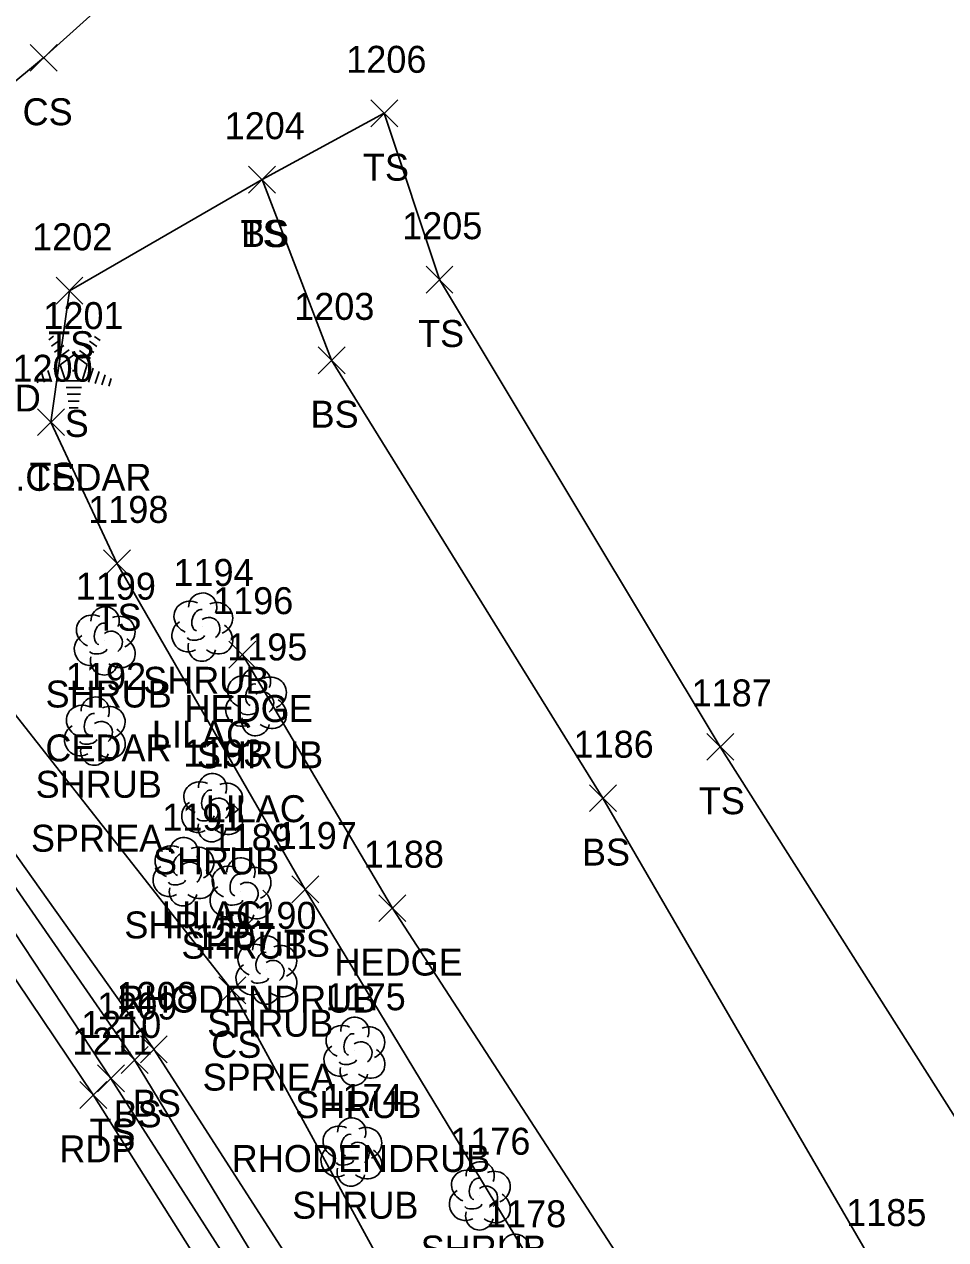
# Model space of a CAD drawing. Extents: x 1501299 to 1502485, y 381423 to 383765.
# Drawn here: x 1501819.8 to 1501888.1, y 382999.5 to 383089.7 of the extents above; entities that cross this region are included whole.
import ezdxf

# ---------------------------------------------------------------- set-up
doc = ezdxf.new("R2010")
doc.units = 0
for name, color, linetype in [('L_A', 7, 'Continuous'), ('L_C', 7, 'Continuous'), ('L_I', 7, 'Continuous'), ('L_TIC', 7, 'Continuous'), ('LAHR', 7, 'Continuous'), ('LELB', 7, 'Continuous'), ('LSH', 7, 'Continuous'), ('LTC', 7, 'Continuous'), ('P_A', 7, 'Continuous'), ('P_I', 7, 'Continuous'), ('P_TIC', 7, 'Continuous'), ('PET', 7, 'Continuous')]:
    doc.layers.add(name, color=color, linetype=linetype)

msp = doc.modelspace()

# ---------------------------------------------------------------- linework, layer by layer
at = {"layer": 'L_TIC'}
for points in [[(1501820.181, 383086.198), (1501822.181, 383088.198)], [(1501822.181, 383086.198), (1501820.181, 383088.198)], [(1501845.451, 383082.089), (1501847.451, 383084.089)], [(1501847.451, 383082.089), (1501845.451, 383084.089)], [(1501845.451, 383082.089), (1501847.451, 383084.089)], [(1501847.451, 383082.089), (1501845.451, 383084.089)], [(1501836.382, 383077.164), (1501838.382, 383079.164)], [(1501838.382, 383077.164), (1501836.382, 383079.164)], [(1501836.382, 383077.164), (1501838.382, 383079.164)], [(1501838.382, 383077.164), (1501836.382, 383079.164)], [(1501849.544, 383069.745), (1501851.544, 383071.745)], [(1501851.544, 383069.745), (1501849.544, 383071.745)], [(1501822.102, 383068.918), (1501824.102, 383070.918)], [(1501824.102, 383068.918), (1501822.102, 383070.918)], [(1501841.537, 383063.759), (1501843.537, 383065.759)], [(1501843.537, 383063.759), (1501841.537, 383065.759)], [(1501820.728, 383059.169), (1501822.728, 383061.169)], [(1501822.728, 383059.169), (1501820.728, 383061.169)], [(1501825.615, 383048.697), (1501827.615, 383050.697)], [(1501827.615, 383048.697), (1501825.615, 383050.697)], [(1501834.929, 383041.926), (1501836.929, 383043.926)], [(1501836.929, 383041.926), (1501834.929, 383043.926)], [(1501870.363, 383035.084), (1501872.363, 383037.084)], [(1501872.363, 383035.084), (1501870.363, 383037.084)], [(1501861.664, 383031.275), (1501863.664, 383033.275)], [(1501863.664, 383031.275), (1501861.664, 383033.275)], [(1501839.589, 383024.507), (1501841.589, 383026.507)], [(1501841.589, 383024.507), (1501839.589, 383026.507)], [(1501846.051, 383023.115), (1501848.051, 383025.115)], [(1501848.051, 383023.115), (1501846.051, 383025.115)], [(1501834.173, 383017.012), (1501836.173, 383019.012)], [(1501836.173, 383017.012), (1501834.173, 383019.012)], [(1501828.357, 383012.645), (1501830.357, 383014.645)], [(1501830.357, 383012.645), (1501828.357, 383014.645)], [(1501826.93, 383011.856), (1501828.93, 383013.856)], [(1501828.93, 383011.856), (1501826.93, 383013.856)], [(1501825.17, 383010.487), (1501827.17, 383012.487)], [(1501827.17, 383010.487), (1501825.17, 383012.487)]]:
    msp.add_lwpolyline(points, dxfattribs=at)
at = {"layer": 'LAHR'}
msp.add_lwpolyline([(1501886.886, 382958.595), (1501878.558, 382964.802), (1501870.803, 382987.478), (1501847.051, 383024.115), (1501835.929, 383042.926)], dxfattribs=at)
at = {"layer": 'LELB'}
for points in [[(1501869.881, 382950.686), (1501868.769, 382950.2), (1501850.126, 382976.258), (1501827.93, 383012.856), (1501805.246, 383045.654), (1501793.264, 383066.917), (1501794.32, 383067.431), (1501799.894, 383080.741), (1501815.831, 383095.832), (1501838.892, 383122.309)], [(1501872.664, 382953.638), (1501855.947, 382979.919), (1501835.173, 383018.012), (1501808.759, 383051.568), (1501808.19, 383064.923), (1501807.021, 383075.451), (1501821.181, 383087.198), (1501841.551, 383105.554)], [(1501860.53, 382958.003), (1501859.863, 382956.699), (1501869.315, 382947.686), (1501873.642, 382949.922), (1501872.664, 382953.638), (1501875.496, 382965.587), (1501865.678, 382984.07), (1501840.589, 383025.507), (1501826.615, 383049.697), (1501821.728, 383060.169), (1501823.102, 383069.918), (1501837.382, 383078.164), (1501846.451, 383083.089)], [(1501875.496, 382965.587), (1501878.558, 382964.802), (1501896.791, 382979.516), (1501894.945, 382998.888), (1501871.363, 383036.084), (1501850.544, 383070.745), (1501846.451, 383083.089)], [(1501860.53, 382958.003), (1501849.203, 382975.471), (1501826.17, 383011.487), (1501803.928, 383045.204), (1501790.589, 383066.151), (1501793.35, 383069.124), (1501796.83, 383082.637)], [(1501869.881, 382950.686), (1501852.369, 382977.849), (1501829.357, 383013.645), (1501805.875, 383046.715), (1501796.137, 383066.958), (1501799.894, 383080.741)], [(1501896.791, 382979.516), (1501889.637, 382987.154), (1501882.83, 382997.53), (1501862.664, 383032.275), (1501842.537, 383064.759), (1501837.382, 383078.164)]]:
    msp.add_lwpolyline(points, dxfattribs=at)
at = {"layer": 'LSH'}
for p, q in [((1501832.935, 383045.019), (1501832.935, 383045.019)), ((1501832.935, 383045.019), (1501832.935, 383045.019)), ((1501825.696, 383044.001), (1501825.696, 383044.001)), ((1501825.696, 383044.001), (1501825.696, 383044.001)), ((1501836.92, 383039.494), (1501836.92, 383039.494)), ((1501836.92, 383039.494), (1501836.92, 383039.494)), ((1501824.958, 383037.303), (1501824.958, 383037.303)), ((1501824.958, 383037.303), (1501824.958, 383037.303)), ((1501833.664, 383031.619), (1501833.664, 383031.619)), ((1501833.664, 383031.619), (1501833.664, 383031.619)), ((1501831.537, 383026.87), (1501831.537, 383026.87)), ((1501831.537, 383026.87), (1501831.537, 383026.87)), ((1501835.77, 383025.367), (1501835.77, 383025.367)), ((1501835.77, 383025.367), (1501835.77, 383025.367)), ((1501837.684, 383019.58), (1501837.684, 383019.58)), ((1501837.684, 383019.58), (1501837.684, 383019.58)), ((1501844.213, 383013.541), (1501844.213, 383013.541)), ((1501844.213, 383013.541), (1501844.213, 383013.541)), ((1501843.989, 383006.078), (1501843.989, 383006.078)), ((1501843.989, 383006.078), (1501843.989, 383006.078)), ((1501853.515, 383002.824), (1501853.515, 383002.824)), ((1501853.515, 383002.824), (1501853.515, 383002.824))]:
    msp.add_line(p, q, dxfattribs=at)
for centre in [(1501832.982, 383046.453), (1501825.743, 383045.435), (1501836.967, 383040.928), (1501825.005, 383038.737), (1501833.711, 383033.053), (1501831.583, 383028.304), (1501835.817, 383026.801), (1501837.731, 383021.014), (1501844.26, 383014.975), (1501844.035, 383007.512), (1501853.562, 383004.258), (1501856.163, 382998.878)]:
    msp.add_arc(centre, 1.047, 335.52715, 180.95627, dxfattribs=at)
for centre, major_axis, ratio, start_param, end_param in [((1501832.143, 383045.685), (1.21, -0.512), 0.895232, 1.570796, 4.712389), ((1501832.726, 383045.477), (-0.208, -0.792), 0.645439, 3.141593, 6.283185), ((1501833.976, 383045.602), (-1.141, -0.483), 0.949671, 1.570796, 4.712389), ((1501824.904, 383044.667), (1.21, -0.512), 0.895232, 1.570796, 4.712389), ((1501825.488, 383044.459), (-0.208, -0.792), 0.645439, 3.141593, 6.283185), ((1501826.738, 383044.584), (-1.141, -0.483), 0.949671, 1.570796, 4.712389), ((1501831.852, 383044.31), (0.584, -1.042), 0.959034, 3.141593, 6.283185), ((1501833.435, 383044.852), (-0.5, 0.667), 0.989748, 3.141593, 6.283185), ((1501824.613, 383043.292), (0.584, -1.042), 0.959034, 3.141593, 6.283185), ((1501826.196, 383043.834), (-0.5, 0.667), 0.989748, 3.141593, 6.283185), ((1501832.477, 383044.269), (-0.625, -0.083), 0.423636, 0, 3.141593), ((1501833.935, 383044.186), (-1.09, 0.792), 0.841452, 1.570796, 4.712389), ((1501826.696, 383043.167), (-1.09, 0.792), 0.841452, 1.570796, 4.712389), ((1501832.935, 383043.519), (0.265, 1.061), 0.942809, 1.570796, 4.712389), ((1501825.696, 383042.501), (0.265, 1.061), 0.942809, 1.570796, 4.712389), ((1501825.238, 383043.251), (-0.625, -0.083), 0.423636, 0, 3.141593), ((1501836.128, 383040.16), (1.21, -0.512), 0.895232, 1.570796, 4.712389), ((1501836.711, 383039.952), (-0.208, -0.792), 0.645439, 3.141593, 6.283185), ((1501837.961, 383040.077), (-1.141, -0.483), 0.949671, 1.570796, 4.712389), ((1501835.837, 383038.785), (0.584, -1.042), 0.959034, 3.141593, 6.283185), ((1501837.42, 383039.327), (-0.5, 0.667), 0.989748, 3.141593, 6.283185), ((1501824.166, 383037.969), (1.21, -0.512), 0.895232, 1.570796, 4.712389), ((1501826, 383037.886), (-1.141, -0.483), 0.949671, 1.570796, 4.712389), ((1501837.92, 383038.661), (-1.09, 0.792), 0.841452, 1.570796, 4.712389), ((1501824.75, 383037.761), (-0.208, -0.792), 0.645439, 3.141593, 6.283185), ((1501825.458, 383037.136), (-0.5, 0.667), 0.989748, 3.141593, 6.283185), ((1501836.92, 383037.994), (0.265, 1.061), 0.942809, 1.570796, 4.712389), ((1501836.462, 383038.744), (-0.625, -0.083), 0.423636, 0, 3.141593), ((1501823.875, 383036.594), (0.584, -1.042), 0.959034, 3.141593, 6.283185), ((1501825.958, 383036.47), (-1.09, 0.792), 0.841452, 1.570796, 4.712389), ((1501824.5, 383036.553), (-0.625, -0.083), 0.423636, 0, 3.141593), ((1501824.958, 383035.803), (0.265, 1.061), 0.942809, 1.570796, 4.712389), ((1501832.873, 383032.286), (1.21, -0.512), 0.895232, 1.570796, 4.712389), ((1501834.706, 383032.203), (-1.141, -0.483), 0.949671, 1.570796, 4.712389), ((1501833.456, 383032.077), (-0.208, -0.792), 0.645439, 3.141593, 6.283185), ((1501832.581, 383030.91), (0.584, -1.042), 0.959034, 3.141593, 6.283185), ((1501834.165, 383031.452), (-0.5, 0.667), 0.989748, 3.141593, 6.283185), ((1501834.665, 383030.786), (-1.09, 0.792), 0.841452, 1.570796, 4.712389), ((1501833.206, 383030.869), (-0.625, -0.083), 0.423636, 0, 3.141593), ((1501833.665, 383030.119), (0.265, 1.061), 0.942809, 1.570796, 4.712389), ((1501830.745, 383027.537), (1.21, -0.512), 0.895232, 1.570796, 4.712389), ((1501831.328, 383027.329), (-0.208, -0.792), 0.645439, 3.141593, 6.283185), ((1501832.578, 383027.454), (-1.141, -0.483), 0.949671, 1.570796, 4.712389), ((1501830.454, 383026.162), (0.584, -1.042), 0.959034, 3.141593, 6.283185), ((1501832.037, 383026.704), (-0.5, 0.667), 0.989748, 3.141593, 6.283185), ((1501834.978, 383026.033), (1.21, -0.512), 0.895232, 1.570796, 4.712389), ((1501836.812, 383025.95), (-1.141, -0.483), 0.949671, 1.570796, 4.712389), ((1501832.537, 383026.037), (-1.09, 0.792), 0.841452, 1.570796, 4.712389), ((1501835.562, 383025.825), (-0.208, -0.792), 0.645439, 3.141593, 6.283185), ((1501831.537, 383025.37), (0.265, 1.061), 0.942809, 1.570796, 4.712389), ((1501831.079, 383026.12), (-0.625, -0.083), 0.423636, 0, 3.141593), ((1501834.687, 383024.658), (0.584, -1.042), 0.959034, 3.141593, 6.283185), ((1501836.27, 383025.2), (-0.5, 0.667), 0.989748, 3.141593, 6.283185), ((1501836.77, 383024.534), (-1.09, 0.792), 0.841452, 1.570796, 4.712389), ((1501835.312, 383024.617), (-0.625, -0.083), 0.423636, 0, 3.141593), ((1501835.77, 383023.867), (0.265, 1.061), 0.942809, 1.570796, 4.712389), ((1501836.892, 383020.247), (1.21, -0.512), 0.895232, 1.570796, 4.712389), ((1501837.475, 383020.039), (-0.208, -0.792), 0.645439, 3.141593, 6.283185), ((1501838.725, 383020.164), (-1.141, -0.483), 0.949671, 1.570796, 4.712389), ((1501836.601, 383018.872), (0.584, -1.042), 0.959034, 3.141593, 6.283185), ((1501838.184, 383019.414), (-0.5, 0.667), 0.989748, 3.141593, 6.283185), ((1501838.684, 383018.747), (-1.09, 0.792), 0.841452, 1.570796, 4.712389), ((1501837.684, 383018.08), (0.265, 1.061), 0.942809, 1.570796, 4.712389), ((1501837.226, 383018.83), (-0.625, -0.083), 0.423636, 0, 3.141593), ((1501843.421, 383014.207), (1.21, -0.512), 0.895232, 1.570796, 4.712389), ((1501845.255, 383014.124), (-1.141, -0.483), 0.949671, 1.570796, 4.712389), ((1501844.005, 383013.999), (-0.208, -0.792), 0.645439, 3.141593, 6.283185), ((1501843.13, 383012.832), (0.584, -1.042), 0.959034, 3.141593, 6.283185), ((1501844.713, 383013.374), (-0.5, 0.667), 0.989748, 3.141593, 6.283185), ((1501845.213, 383012.707), (-1.09, 0.792), 0.841452, 1.570796, 4.712389), ((1501843.755, 383012.791), (-0.625, -0.083), 0.423636, 0, 3.141593), ((1501844.213, 383012.041), (0.265, 1.061), 0.942809, 1.570796, 4.712389), ((1501843.197, 383006.745), (1.21, -0.512), 0.895232, 1.570796, 4.712389), ((1501843.78, 383006.536), (-0.208, -0.792), 0.645439, 3.141593, 6.283185), ((1501845.03, 383006.662), (-1.141, -0.483), 0.949671, 1.570796, 4.712389), ((1501842.906, 383005.37), (0.584, -1.042), 0.959034, 3.141593, 6.283185), ((1501844.489, 383005.912), (-0.5, 0.667), 0.989748, 3.141593, 6.283185), ((1501844.989, 383005.245), (-1.09, 0.792), 0.841452, 1.570796, 4.712389), ((1501843.989, 383004.578), (0.265, 1.061), 0.942809, 1.570796, 4.712389), ((1501843.531, 383005.328), (-0.625, -0.083), 0.423636, 0, 3.141593), ((1501852.724, 383003.491), (1.21, -0.512), 0.895232, 1.570796, 4.712389), ((1501854.557, 383003.408), (-1.141, -0.483), 0.949671, 1.570796, 4.712389), ((1501853.307, 383003.283), (-0.208, -0.792), 0.645439, 3.141593, 6.283185), ((1501852.432, 383002.116), (0.584, -1.042), 0.959034, 3.141593, 6.283185), ((1501854.015, 383002.658), (-0.5, 0.667), 0.989748, 3.141593, 6.283185), ((1501854.516, 383001.991), (-1.09, 0.792), 0.841452, 1.570796, 4.712389), ((1501853.057, 383002.074), (-0.625, -0.083), 0.423636, 0, 3.141593), ((1501853.516, 383001.324), (0.265, 1.061), 0.942809, 1.570796, 4.712389)]:
    msp.add_ellipse(centre, major_axis=major_axis, ratio=ratio, start_param=start_param, end_param=end_param, dxfattribs=at)
at = {"layer": 'LTC'}
for p, q in [((1501821.56, 383066.284), (1501821.915, 383066.541)), ((1501821.77, 383065.819), (1501822.299, 383066.203)), ((1501824.587, 383066.176), (1501825.137, 383065.777)), ((1501824.959, 383066.524), (1501825.378, 383066.22)), ((1501821.98, 383065.353), (1501822.683, 383065.864)), ((1501822.189, 383064.887), (1501823.067, 383065.525)), ((1501822.414, 383064.432), (1501823.425, 383065.166)), ((1501823.425, 383065.166), (1501824.422, 383064.441)), ((1501823.845, 383065.479), (1501824.655, 383064.891)), ((1501824.217, 383065.828), (1501824.896, 383065.334)), ((1501821.959, 383064.213), (1501822.29, 383063.194)), ((1501822.414, 383064.432), (1501822.801, 383063.239)), ((1501824.422, 383064.441), (1501824.031, 383063.239)), ((1501824.86, 383064.171), (1501824.522, 383063.131)), ((1501820.593, 383063.563), (1501820.745, 383063.095)), ((1501821.048, 383063.78), (1501821.26, 383063.128)), ((1501821.504, 383063.996), (1501821.775, 383063.161)), ((1501824.031, 383063.239), (1501822.801, 383063.239)), ((1501825.305, 383063.92), (1501825.017, 383063.036)), ((1501825.749, 383063.67), (1501825.512, 383062.941)), ((1501826.193, 383063.42), (1501826.007, 383062.846)), ((1501823.993, 383062.739), (1501822.848, 383062.739)), ((1501823.909, 383062.239), (1501822.921, 383062.239)), ((1501823.825, 383061.739), (1501822.994, 383061.739)), ((1501823.742, 383061.239), (1501823.067, 383061.239))]:
    msp.add_line(p, q, dxfattribs=at)
at = {"layer": 'P_TIC'}
for points in [[(1501823.868, 383009.254), (1501825.868, 383011.254)], [(1501825.868, 383009.254), (1501823.868, 383011.254)]]:
    msp.add_lwpolyline(points, dxfattribs=at)
at = {"layer": 'PET'}
msp.add_lwpolyline([(1501971.372, 382720.654), (1501961.032, 382754.708), (1501942.926, 382798.84), (1501930.998, 382825.078), (1501924.576, 382839.599), (1501916.528, 382851.603), (1501908.311, 382868.386), (1501899.175, 382885.527), (1501887.899, 382904.195), (1501878.505, 382922.493), (1501869.738, 382936.529), (1501858.065, 382956.489), (1501847.469, 382974.349), (1501824.868, 383010.254), (1501802.294, 383043.804), (1501787.994, 383066.094), (1501768.484, 383096.751)], dxfattribs=at)

# ---------------------------------------------------------------- texts
at = {"layer": 'L_A'}
for s, p in [('CS', (1501819.622, 383082.198)), ('TS', (1501844.861, 383078.089)), ('TS', (1501844.861, 383078.089)), ('TS', (1501835.791, 383073.164)), ('BS', (1501835.823, 383073.164)), ('TS', (1501848.954, 383065.745)), ('TS', (1501821.512, 383064.918)), ('BS', (1501840.978, 383059.759)), ('S', (1501822.751, 383059.076)), ('TS', (1501820.138, 383055.169)), ('TS', (1501825.024, 383044.697)), ('SHRUB', (1501828.565, 383040.019)), ('SHRUB', (1501821.326, 383039.001)), ('HEDGE', (1501831.63, 383037.926)), ('SHRUB', (1501832.55, 383034.494)), ('SHRUB', (1501820.588, 383032.303)), ('TS', (1501869.773, 383031.084)), ('BS', (1501861.105, 383027.275)), ('SHRUB', (1501829.294, 383026.619)), ('SHRUB', (1501827.167, 383021.87)), ('SHRUB', (1501831.4, 383020.367)), ('TS', (1501838.999, 383020.507)), ('HEDGE', (1501842.752, 383019.115)), ('SHRUB', (1501833.314, 383014.58)), ('CS', (1501833.614, 383013.012)), ('BS', (1501827.798, 383008.645)), ('SHRUB', (1501839.843, 383008.541)), ('BS', (1501826.371, 383007.856)), ('TS', (1501824.58, 383006.487)), ('SHRUB', (1501839.619, 383001.078)), ('SHRUB', (1501849.145, 382997.824))]:
    msp.add_text(s, height=2, dxfattribs=at).set_placement(p)
at = {"layer": 'L_C'}
for s, p in [('DOGWOOD', (1501806.27, 383060.962)), ('L.CEDAR', (1501817.594, 383055.076)), ('LILAC', (1501829.211, 383036.019)), ('CEDAR', (1501821.31, 383035.001)), ('LILAC', (1501833.196, 383030.494)), ('SPRIEA', (1501820.242, 383028.303)), ('LILAC', (1501829.94, 383022.619)), ('RHODENDRUB', (1501826.691, 383016.367)), ('SPRIEA', (1501832.968, 383010.58)), ('RHODENDRUB', (1501835.135, 383004.541))]:
    msp.add_text(s, height=2, dxfattribs=at).set_placement(p)
at = {"layer": 'L_I'}
for s, p in [('1206', (1501843.625, 383086.089)), ('1206', (1501843.625, 383086.089)), ('1204', (1501834.61, 383081.164)), ('1204', (1501834.61, 383081.164)), ('1202', (1501820.331, 383072.918)), ('1205', (1501847.773, 383073.745)), ('1203', (1501839.765, 383067.759)), ('1201', (1501821.161, 383067.076)), ('1200', (1501818.87, 383063.169)), ('1198', (1501824.489, 383052.697)), ('1194', (1501830.809, 383048.019)), ('1199', (1501823.562, 383047.001)), ('1196', (1501833.748, 383045.926)), ('1195', (1501834.794, 383042.494)), ('1192', (1501822.832, 383040.303)), ('1187', (1501869.238, 383039.084)), ('1186', (1501860.483, 383035.275)), ('1193', (1501831.539, 383034.619)), ('1191', (1501829.978, 383029.87)), ('1189', (1501833.637, 383028.367)), ('1197', (1501838.463, 383028.507)), ('1188', (1501844.925, 383027.115)), ('1190', (1501835.472, 383022.58)), ('1207', (1501832.401, 383021.012)), ('1208', (1501826.585, 383016.645)), ('1175', (1501842.088, 383016.541)), ('1209', (1501825.15, 383015.856)), ('1210', (1501823.958, 383014.487)), ('1174', (1501841.863, 383009.078)), ('1176', (1501851.335, 383005.824)), ('1178', (1501853.991, 383000.444)), ('1185', (1501880.705, 383000.53))]:
    msp.add_text(s, height=2, dxfattribs=at).set_placement(p)
at = {"layer": 'LTC'}
msp.add_text('.', height=1.037, rotation=270, dxfattribs=at).set_placement((1501823.308, 383064.18))
at = {"layer": 'P_A'}
msp.add_text('RDP', height=2, dxfattribs=at).set_placement((1501822.356, 383005.254))
at = {"layer": 'P_I'}
msp.add_text('1211', height=2, dxfattribs=at).set_placement((1501823.309, 383013.254))

doc.saveas('drawing.dxf')
